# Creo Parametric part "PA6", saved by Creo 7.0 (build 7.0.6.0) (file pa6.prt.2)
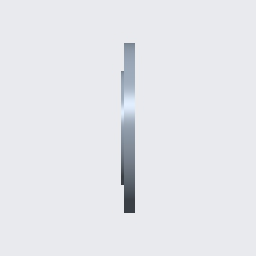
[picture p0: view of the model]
Units: Inch lbm Second (Pro/E Default); INCH, POUND, SECS

Created from: XX_INLBS_PART_SOLID_ABS.PRT

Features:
  1. datum plane "RIGHT"
  2. datum plane "TOP"
  3. datum plane "FRONT"
  4. coordinate system
  5. revolve "Revolve 1"
  6. pattern "Pattern 1"
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
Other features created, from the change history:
  hole "Hole 1" (2 times)
  pattern "Pattern 1"
  hole "Hole 1 [2]" (2 times)
  hole "Hole 1 [3]" (2 times)
  hole "Hole 1 [4]" (2 times)
  hole "Hole 2"
  pattern "Pattern 2"
  hole "Hole 2 [2]"
  hole "Hole 2 [3]"
  hole "Hole 2 [4]"
  hole "Hole 2 [5]"
  hole "Hole 2 [6]"
  chamfer "Chamfer 1"
  planar section "XSEC0001"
